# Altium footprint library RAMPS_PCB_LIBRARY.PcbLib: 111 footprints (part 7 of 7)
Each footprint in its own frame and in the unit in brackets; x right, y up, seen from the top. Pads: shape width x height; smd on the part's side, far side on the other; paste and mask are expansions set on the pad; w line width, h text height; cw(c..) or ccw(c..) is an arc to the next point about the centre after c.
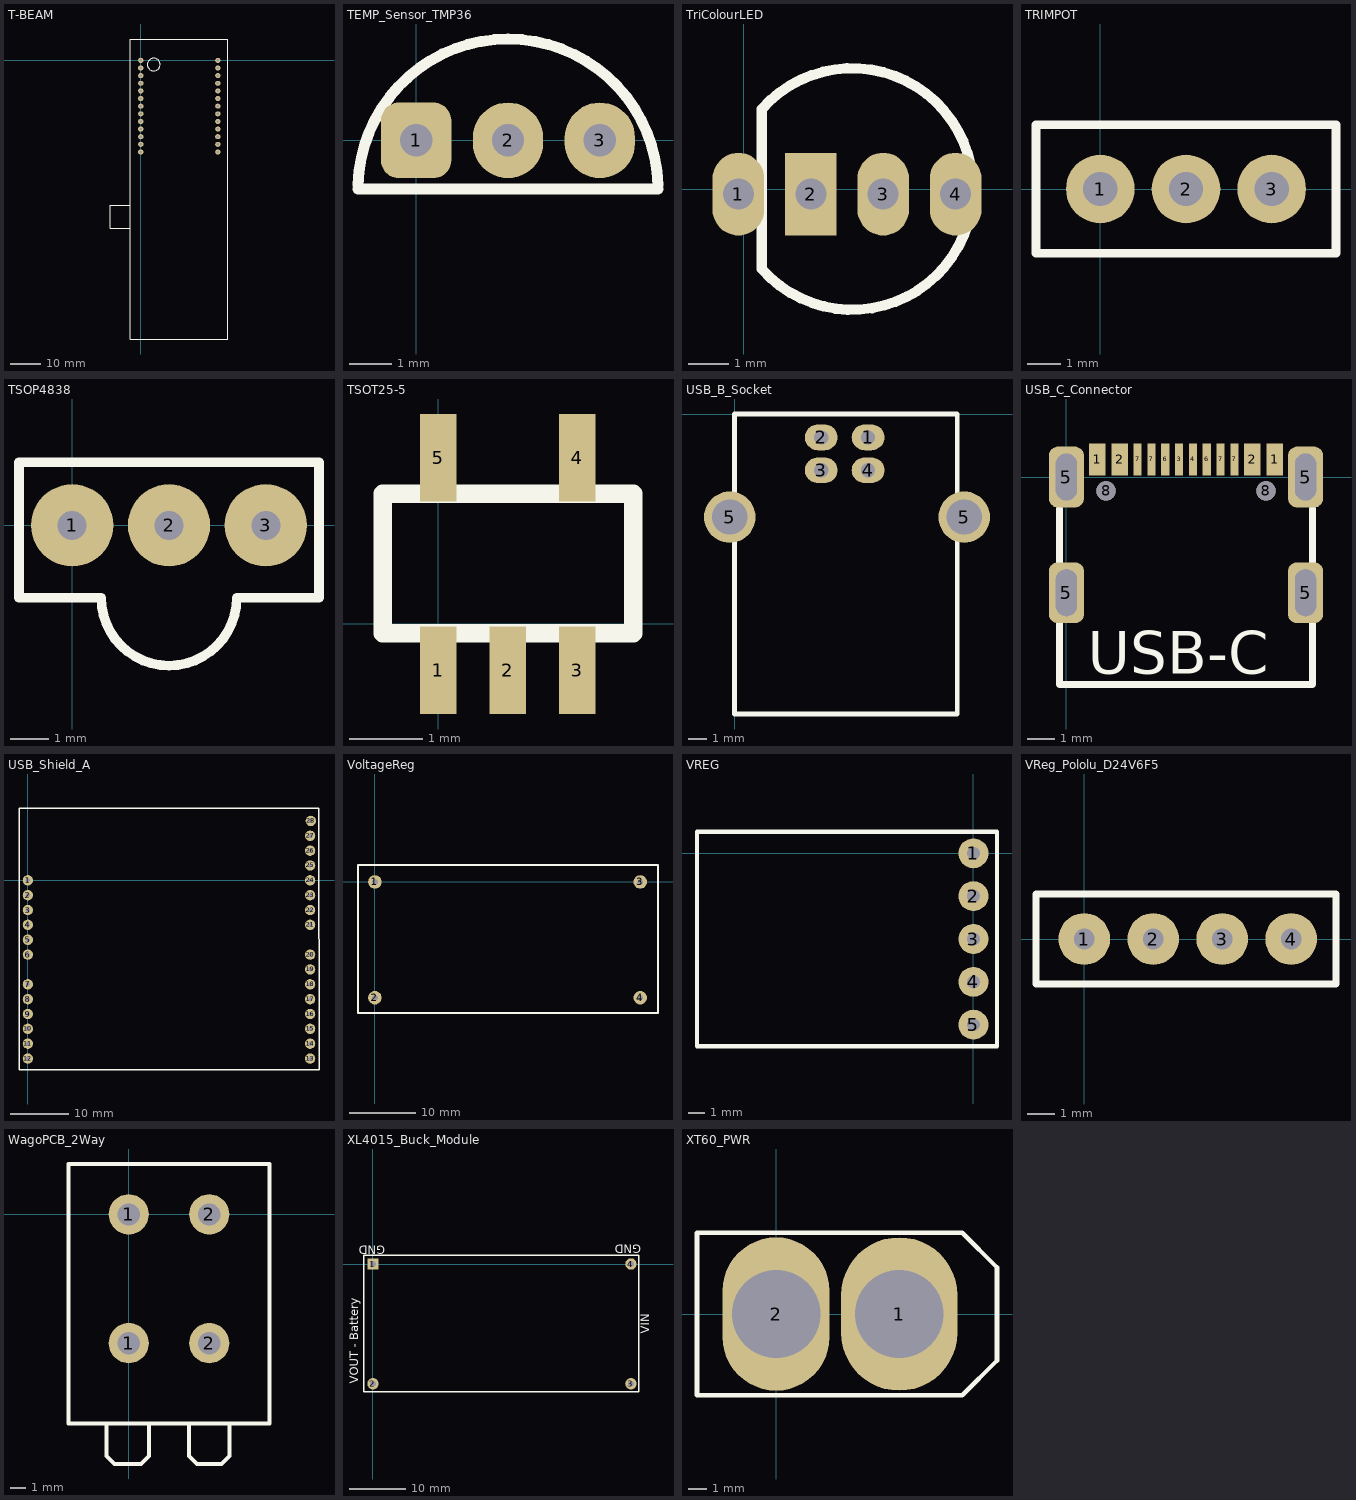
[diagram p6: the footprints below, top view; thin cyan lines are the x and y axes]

## T-BEAM [mil]
pads (26):
  oval 70x65 hole 30: 1(0,0) 2(0,-100) 3(0,-200) 4(0,-300) 5(0,-400) 6(0,-500) 7(0,-600) 8(0,-700) 9(0,-800) 10(0,-900) 11(0,-1000) 12(0,-1100) 13(0,-1200) 14(1010,-1200) 15(1010,-1100) 16(1010,-1000) 17(1010,-900) 18(1010,-800) 19(1010,-700) 20(1010,-600) 21(1010,-500) 22(1010,-400) 23(1010,-300) 24(1010,-200) 25(1010,-100) 26(1010,0)
Top Overlay:
  circle w10: c170,-55 r83.22
  lines w10: -140,-2200 -400,-2200 -400,-1900 -140,-1900 ; -140,-1850 -135,-1845 ; -140,-3650 -140,280 1140,280 1140,-3650 -140,-3650

## TEMP_Sensor_TMP36 [mil]
pads (3):
  rrect50% 65x70 hole 30: 1(0,0)
  oval 65x70 hole 30: 2(85,0) 3(170,0)
Top Overlay:
  lines w10: -53.76,-45 223.77,-45 ; -53.76,-41.17 cw(c85,-45) 223.77,-41.38

## TriColourLED [mil]
pads (4):
  oval 50x80 hole 30: 1(-5,-5) 3(135,-5) 4(205,-5)
  rect 50x80 hole 30: 2(65,-5)
Top Overlay:
  lines w10: 17.51,77.27 cw(c105,0) 18.01,-77.83 ; 17.53,-77.23 17.53,77.27

## TRIMPOT [mil]
pads (3):
  round 80 hole 40: 1(0,0) 2(100,0) 3(200,0)
Top Overlay:
  lines w10: -75,-75 -75,75 275,75 275,-75 -75,-75

## TSOP4838 [mil]
pads (3):
  round 85 hole 30: 1(0,0) 2(100,0) 3(200,0)
Top Overlay:
  lines w10: -55,-75 30,-75 ccw(c100,-75) 170,-75 255,-75 255,65 -55,65 -55,-75

## TSOT25-5 [mm]
pads (5):
  rect 0.5x1.2 smd: 1(0,-0.635) 2(0.95,-0.635) 3(1.9,-0.635) 4(1.9,2.273) 5(0,2.273)
Top Overlay:
  lines w0.254: -0.762,-0.127 2.667,-0.127 2.667,1.778 -0.762,1.778 -0.762,-0.127

## USB_B_Socket [mil]
pads (6):
  oval 70x55 hole 30: 1(285,-50) 2(185,-50) 3(185,-120) 4(285,-120)
  round 110 hole 75: 5(-10,-220) 5(490,-220)
Top Overlay:
  lines w10: 0,-640 475,-640 475,0 0,0 0,-640

## USB_C_Connector [mm] "LCSC: C2988369"
pads (18):
  rect 0.6x1.15 smd: 1(1.12,0.635) 1(7.52,0.635) 2(1.92,0.635) 2(6.72,0.635)
  rect 0.3x1.15 smd: 3(4.07,0.635) 4(4.57,0.635) 6(3.57,0.635) 6(5.07,0.635) 7(2.57,0.635) 7(3.07,0.635) 7(5.57,0.635) 7(6.07,0.635)
  rrect50% 1.27x2.2 hole 0.762 slot 1.7 at 90 deg: 5(0,-4.18) 5(0,0) 5(8.64,-4.18) 5(8.64,0)
  round 0.7 hole 0.7: 8(1.43,-0.5) 8(7.21,-0.5)
Top Overlay:
  lines w0.254: -0.254,-1.143 -0.254,-7.493 8.89,-7.493 8.89,-1.143
  text "USB-C" at 0.762,-7.112 h1.52

## USB_Shield_A [mil]
pads (28):
  round 70 hole 30: 1(0,0) 2(0,-100) 3(0,-200) 4(0,-300) 5(0,-400) 6(0,-500) 7(0,-700) 8(0,-800) 9(0,-900) 10(0,-1000) 11(0,-1100) 12(0,-1200) 13(1900,-1200) 14(1900,-1100) 15(1900,-1000) 16(1900,-900) 17(1900,-800) 18(1900,-700) 19(1900,-600) 20(1900,-500) 21(1900,-300) 22(1900,-200) 23(1900,-100) 24(1900,0) 25(1900,100) 26(1900,200) 27(1900,300) 28(1905,400)
Top Overlay:
  lines w10: -60,-1275 -60,485 1960,485 1960,-1275 -60,-1275

## VoltageReg [mil]
pads (4):
  round 80 hole 35: 1(0,0) 2(0,-685) 3(1570,0) 4(1570,-685)
Top Overlay:
  lines w10: -100,-775 1675,-775 1675,100 -100,100 -100,-775

## VREG [mil]
pads (5):
  round 70 hole 30: 1(0,0) 2(0,-100) 3(0,-200) 4(0,-300) 5(0,-400)
Top Overlay:
  lines w10: -645,-450 55,-450 55,50 -645,50 -645,-450

## VReg_Pololu_D24V6F5 [mil]
pads (4):
  round 75 hole 30: 1(0,0) 2(100,0) 3(200,0) 4(300,0)
Top Overlay:
  lines w10: -70,-65 365,-65 365,65 -70,65 -70,-65

## WagoPCB_2Way [mil]
pads (4):
  round 100 hole 55: 1(0,-320) 1(0,0) 2(200,-320) 2(200,0)
Top Overlay:
  lines w10: -55,-520 -55,-600 -35,-620 30,-620 50,-600 50,-520 ; 150,-520 150,-600 170,-620 230,-620 250,-600 250,-520 ; -150,-520 350,-520 350,125 -150,125 -150,-520

## XL4015_Buck_Module [mil]
pads (4):
  rect 80x80 hole 40: 1(0,0)
  round 80 hole 40: 2(0,-840) 3(1810,-840) 4(1810,0)
Top Overlay:
  lines w10: -65,-895 1865,-895 1865,60 -65,60 -65,-895
  text "VOUT - Battery" at -104.99,-840 h60
  text "VIN" at 1940,-490 h60
  text "GND" at 85,130 h60
  text "GND" at 1883.13,133.81 h60

## XT60_PWR [mil]
pads (2):
  oval 250x330 hole 190: 1(265,0)
  oval 230x330 hole 190: 2(0,0)
Top Overlay:
  lines w10: -170,-175 400,-175 475,-100 475,100 400,175 -170,175 -170,0 -170,-175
